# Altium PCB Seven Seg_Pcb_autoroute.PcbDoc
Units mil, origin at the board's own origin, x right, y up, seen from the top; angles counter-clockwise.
Board outline 6000 x 4000 mil, 2 copper layers (Top Layer, Bottom Layer); 31 components, 44 nets, 140 pads, 0 vias.
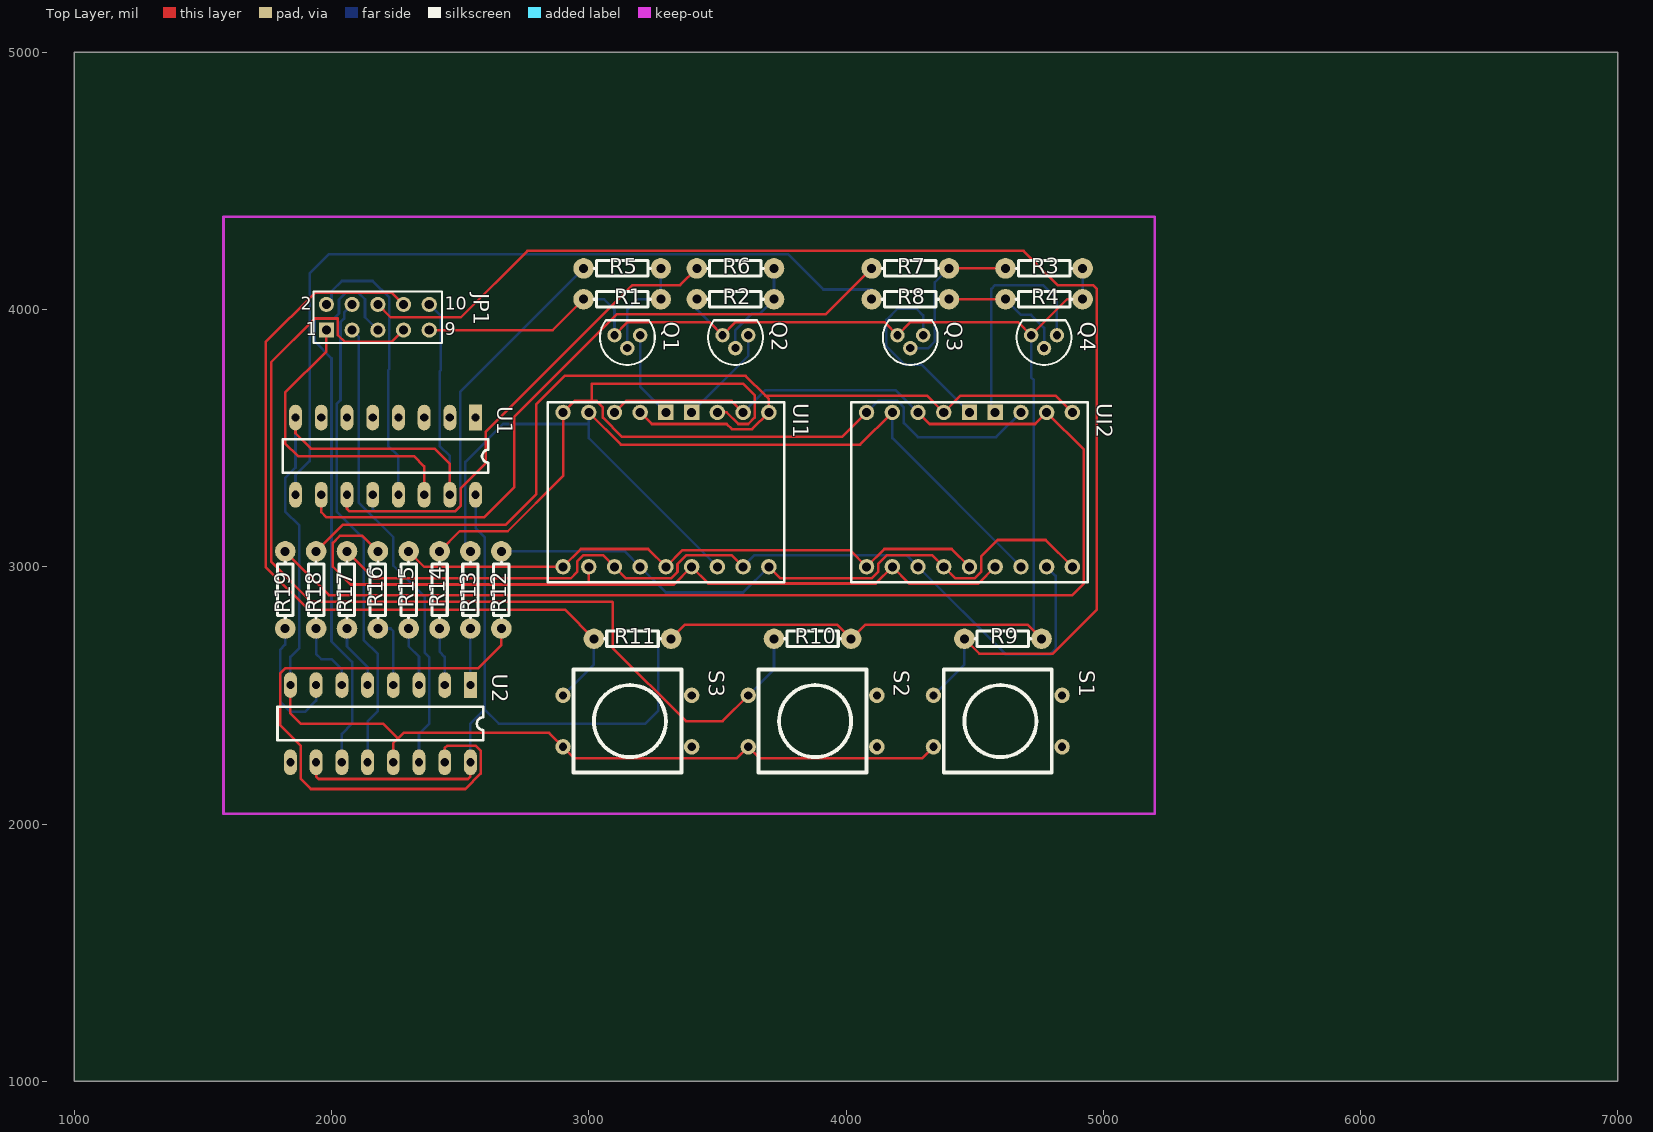
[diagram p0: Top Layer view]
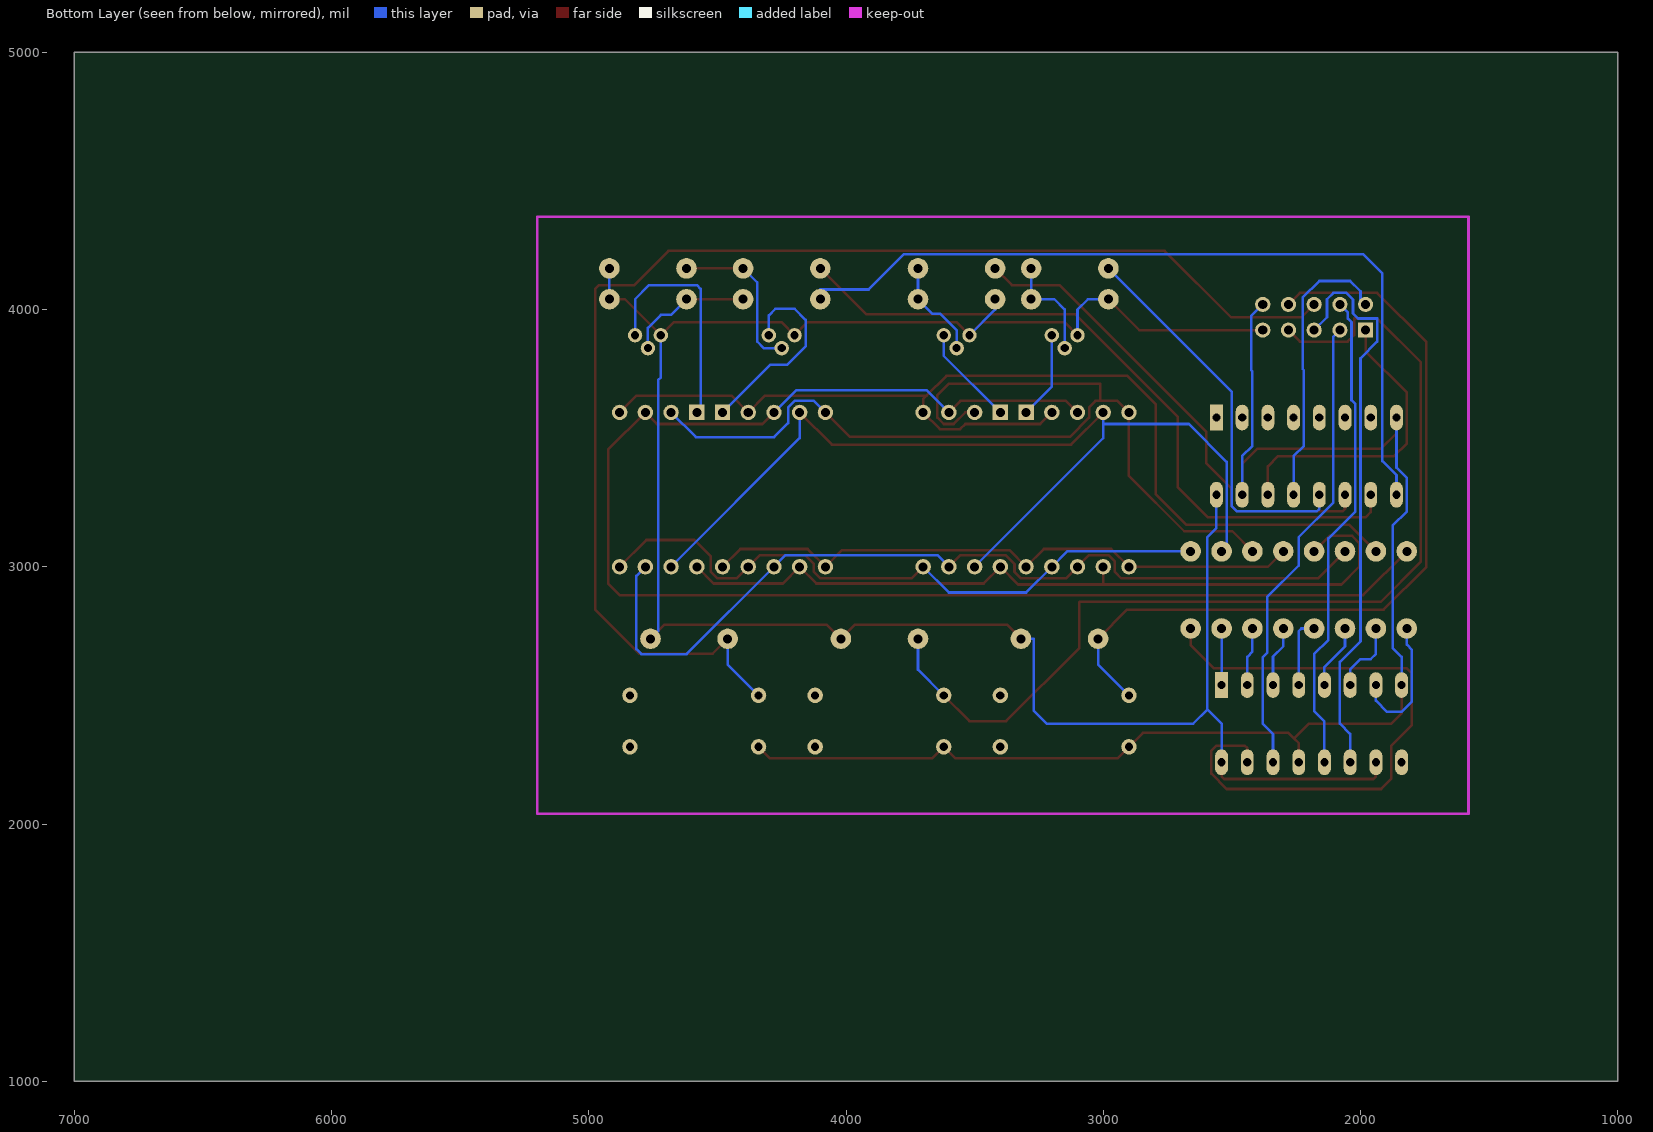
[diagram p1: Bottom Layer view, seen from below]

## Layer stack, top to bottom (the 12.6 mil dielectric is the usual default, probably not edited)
Top Layer: signal copper 1.4
Dielectric: dielectric 12.6, FR-4, Dk 4.8
Bottom Layer: signal copper 1.4

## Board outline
1000,1000 7000,1000 7000,5000 1000,5000

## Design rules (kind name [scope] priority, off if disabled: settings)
Clearance [All] p1: gap=10
ComponentClearance [All] p1: gap=10 collisioncheckmode=0
PolygonConnect [All] p1: connectstyle=Relief reliefconductorwidth=10 reliefentries=4 polygonreliefangle="90 Angle"
RoomDefinition SevenSeg_Sch_04172006 [InComponentClass('SevenSeg_Sch_04172006')] p1: confinementstyle=ConfineIn formatcopy=TRUE outline 1000,1000 7000,1000 7000,4980 1000,4980
RoutingLayers [All] p1: top layer=Horizontal bottom layer=Vertical
RoutingVias [All] p1: holewidth=28 width=50 viastyle="Through Hole" minholewidth=28 minwidth=50 maxholewidth=28 maxwidth=50
SolderMaskExpansion [All] p1: expansion=4
TestPointUsage [All] p1: valid=0 allowmultiple=FALSE
Testpoint [All] p1: side=15 testpointundercomponent=TRUE minsize=40 maxsize=100 preferedsize=60 minholesize=0 maxholesize=40 preferedholesize=32 testpointgrid=1 style=1023 order=-539222988
Width [All] p1: maxlimit=10 minlimit=10 preferedwidth=10
16 further rules are at their usual default settings.

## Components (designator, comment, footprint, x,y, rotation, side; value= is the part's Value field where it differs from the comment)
JP1 "Header 5X2" HDR2X5 1980,3920 r0 top
Q1 "PNP" BC548 3100,3900 r270 top
Q2 "PNP" BC548 3520,3900 r270 top
Q3 "PNP" BC548 4200,3900 r270 top
Q4 "PNP" BC548 4720,3900 r270 top
R1 "10K" RES 3280,4040 r180 top
R2 "10K" RES 3720,4040 r180 top
R3 "10K" RES 4620,4160 r0 top
R4 "10K" RES 4620,4040 r0 top
R5 "10K" RES 2980,4160 r0 top
R6 "10K" RES 3420,4160 r0 top
R7 "10K" RES 4100,4160 r0 top
R8 "10K" RES 4100,4040 r0 top
R9 "10k" RES 4460,2720 r0 top
R10 "10K" RES 3720,2720 r0 top
R11 "10K" RES 3020,2720 r0 top
R12 "220" RES 2660,2760 r90 top
R13 "220" RES 2540,2760 r90 top
R14 "220" RES 2420,2760 r90 top
R15 "220" RES 2300,2760 r90 top
R16 "220" RES 2180,2760 r90 top
R17 "220" RES 2060,2760 r90 top
R18 "220" RES 1940,2760 r90 top
R19 "220" RES 1820,2760 r90 top
S1 "SWITCH PB2" "SWITCH PB2" 4340,2500 r0 top
S2 "SWITCH PB2" "SWITCH PB2" 3620,2500 r0 top
S3 "SWITCH PB2" "SWITCH PB2" 2900,2500 r0 top
U1 "74HC139" DIP16 2560,3580 r270 top
U2 "74HC595" DIP16 2540,2540 r270 top
UI1 "SEVENSEG 2CA" SEVENTSEGMENT2 2900,3600 r0 top
UI2 "SEVENSEG 2CA" SEVENTSEGMENT2 4080,3600 r0 top

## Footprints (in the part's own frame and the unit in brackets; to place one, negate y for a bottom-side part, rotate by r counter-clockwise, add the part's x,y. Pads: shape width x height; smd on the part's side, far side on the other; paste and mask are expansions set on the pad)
BC548 [mil]
  round 56 hole 32: 1(0,0) 2(50,50) 3(0,100)
  silkscreen extent -59,-57 115,157
DIP16 [mil]
  rect 100x50 hole 32: 1(0,0)
  oval 100x50 hole 32: 2(0,-100) 3(0,-200) 4(0,-300) 5(0,-400) 6(0,-500) 7(0,-600) 8(0,-700) 9(300,-700) 10(300,-600) 11(300,-500) 12(300,-400) 13(300,-300) 14(300,-200) 15(300,-100) 16(300,0)
  silkscreen extent 85,-750 215,50
HDR2X5 [mm]
  rect 1.5x1.5 hole 0.9: 1(0,0)
  round 1.5 hole 0.9: 2(0,2.54) 3(2.54,0) 4(2.54,2.54) 5(5.08,0) 6(5.08,2.54) 7(7.62,0) 8(7.62,2.54) 9(10.16,0) 10(10.16,2.54)
  silkscreen extent -1.27,-1.27 11.43,3.81
RES [mil]
  round 80 hole 35: 1(0,0) 2(300,0)
  silkscreen extent 41,-30 259,30
SEVENTSEGMENT2 [mil]
  round 60 hole 35: 1(0,0) 2(100,0) 3(200,0) 4(300,0) 7(600,0) 8(700,0) 9(800,0) 10(800,-600) 11(700,-600) 12(600,-600) 13(500,-600) 14(400,-600) 15(300,-600) 16(200,-600) 17(100,-600) 18(0,-600)
  rect 60x60 hole 35: 5(400,0) 6(500,0)
  silkscreen extent -60,-660 860,40
"SWITCH PB2" [mil]
  round 60 hole 32: 1(0,0) 2(0,-200) 3(500,0) 4(500,-200)
  silkscreen extent 40,-300 460,100

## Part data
JP1: "Header, 5-Pin, Dual row"
Q1 Q2 Q3 Q4: "PNP Transistor"
R1 R2 R3 R4 R5 R6 R7 R8 R9 R10 R11 R12 R13 R14 R15 R16 R17 R18 R19: library part RES
U1: "2-to-4 Decoder"
U2: "8 Bit Shift Register with Output Latches (3 STATE)"

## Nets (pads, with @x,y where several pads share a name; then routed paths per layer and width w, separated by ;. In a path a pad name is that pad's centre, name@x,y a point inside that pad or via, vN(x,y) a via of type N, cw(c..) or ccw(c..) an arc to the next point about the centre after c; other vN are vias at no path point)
COM1: Q4.3 UI2.6 | length 919
  Bottom Layer w10: UI2.6 4565,3600 4565,4080 4580,4095 4765,4095 4820,4040 Q4.3
COM2: Q3.3 UI2.5 | length 781
  Bottom Layer w10: Q3.3 4300,3977 4274,4003 4200,4003 4157,3960 4157,3857 4228,3786 4294,3786 UI2.5
COM3: Q2.3 UI1.6 | length 391.1
  Bottom Layer w10: UI1.6 3620,3820 Q2.3
COM4: Q1.3 UI1.5 | length 341.4
  Bottom Layer w10: Q1.3 3200,3700 UI1.5
DEC0: JP1.2 U1.13 | length 1124.1
  Bottom Layer w10: JP1.2 2000,4020 2000,4071 2040,4111 2160,4111 2225,4046 2225,3769 2220,3764 2220,3470 2260,3430 U1.13
DEC1: JP1.1 U1.14 | length 1193.6
  Top Layer w10: JP1.1 1980,3837 1820,3677 1820,3480 1870,3430 2320,3430 2360,3390 U1.14
DSER: JP1.3 U2.14 | length 1820.8
  Bottom Layer w10: JP1.3 2105,3895 2105,3250 2240,3115 2240,3005 2363,2882 2363,2665 2380,2648 2380,2390 2340,2350 U2.14
GND: JP1.10 S1.2 S2.2 S3.2 U1.8 U1.15 U2.8 U2.13 | length 5557.5
  Top Layer w10: U2.8 1840,2430 1880,2390 2200,2390 2258,2332 ; U1.8 1860,3519 1920,3459 2401,3459 2460,3400 U1.15 ; U2.13 2240,2314 2258,2332 ; S1.2 4295,2255 3665,2255 S2.2 3575,2255 2945,2255 S3.2 2846,2354 2280,2354 2258,2332
  Bottom Layer w10: U2.8 1840,2650 1875,2685 1875,3160 1820,3215 1820,3345 1860,3385 U1.8 ; JP1.10 2425,3975 2425,3765 2420,3760 2420,3470 2460,3430 U1.15
LED1: R19.2 UI1.3 UI1.8 UI2.3 UI2.8 | length 5744.9
  Top Layer w10: R19.2 1990,2890 4880,2890 4925,2935 4925,3455 UI2.8 4735,3555 4325,3555 UI2.3 ; UI1.3 3145,3645 3555,3645 UI1.8
  Bottom Layer w10: UI1.8 3686,3686 4194,3686 UI2.3
LED2: R18.2 UI1.4 UI1.9 UI2.4 UI2.9 | length 4163.8
  Top Layer w10: R18.2 2043,3163 2676,3163 2796,3283 2796,3632 2906,3742 3610,3742 3687,3665 ; UI1.4 3245,3555 3536,3555 3556,3535 3635,3535 UI1.9 3700,3652 3687,3665 ; UI2.9 4815,3665 4445,3665 UI2.4 4315,3665 3687,3665
LED3: R17.2 UI1.11 UI1.16 UI2.11 UI2.16 | length 3490.9
  Top Layer w10: R17.2 2165,2955 2930,2955 2955,2980 2955,3020 2980,3045 3055,3045 UI1.16 3145,2955 3320,2955 3345,2980 3345,3010 3380,3045 3555,3045 UI1.11
  Bottom Layer w10: UI1.11 3645,3045 4235,3045 UI2.16 4620,2660 4795,2660 4815,2680 4815,2965 UI2.11
LED4: R16.2 UI1.13 UI1.17 UI2.13 UI2.17 | length 3112.9
  Top Layer w10: R16.2 2120,3120 2032,3120 2005,3093 2005,3000 2074,2931 3000,2931 ; UI1.17 3000,2931 ; UI2.13 4515,2935 4245,2935 UI2.17 4115,2935 3465,2935 UI1.13 3331,2931 3000,2931
LED5: R15.2 UI1.14 UI1.18 UI2.14 UI2.18 | length 2373
  Top Layer w10: R15.2 2360,3000 UI1.18 2969,3069 3231,3069 UI1.14 3365,3065 4015,3065 UI2.18 4149,3069 4411,3069 UI2.14
LED6: R14.2 UI1.1 UI1.7 UI2.1 UI2.7 | length 3900
  Top Layer w10: R14.2 2498,3138 2685,3138 2900,3353 UI1.1 2945,3645 3012,3645 ; UI1.7 3536.36,3600 3581.36,3555 3620,3555 3645,3580 3645,3667 3600,3712 3012,3712 3012,3645 ; UI2.1 3985,3505 3130,3505 3055,3580 3055,3620 3030,3645 3012,3645
  Bottom Layer w10: UI2.1 4125,3645 4200,3645 4225,3620 4225,3559 4280,3504 4584,3504 UI2.7
LED7: R13.2 UI1.2 UI1.12 UI2.2 UI2.12 | length 3806.7
  Top Layer w10: UI1.2 3125,3475 4055,3475 UI2.2
  Bottom Layer w10: R13.2 2520,3060 2520,3408 2667,3555 3000,3555 ; UI1.2 3000,3555 ; UI1.12 3000,3500 3000,3555 ; UI2.2 4180,3500 UI2.12
LED8: R12.2 UI1.10 UI1.15 UI2.10 UI2.15 | length 2578.4
  Top Layer w10: UI1.10 3745,2955 4100,2955 4125,2980 4125,3010 4160,3045 4335,3045 UI2.15 4425,2955 4500,2955 4525,2980 4525,3040 4589,3104 4776,3104 UI2.10
  Bottom Layer w10: R12.2 3140,3060 UI1.15 3300,2900 3600,2900 UI1.10
LSD1: R8.1 U1.9 | length 3193.6
  Bottom Layer w10: U1.9 1860,3356 1915,3411 1915,4140 1990,4215 3775,4215 3912,4078 4100,4078 R8.1
LSD2: R6.1 U1.11 | length 1921.9
  Top Layer w10: U1.11 2060,3225 2070,3215 2480,3215 2503,3238 2503,3306 2600,3403 2600,3525 3170,4095 3355,4095 R6.1
MSD1: R7.1 U1.10 | length 2777.2
  Top Layer w10: U1.10 1960,3212 1980,3192 2593,3192 2710,3309 2710,3582 3110,3982 3922,3982 R7.1
MSD2: R5.1 U1.12 | length 1531.2
  Bottom Layer w10: U1.12 2160,3225 2170,3215 2480,3215 2500,3235 2500,3680 R5.1
NetQ1_2: Q1.2 R1.1 R5.2 | length 416.6
  Bottom Layer w10: Q1.2 3150,4000 3190,4040 R1.1 R5.2
NetQ2_2: Q2.2 R2.1 R6.2 | length 389.7
  Bottom Layer w10: Q2.2 3570,3920 3633,3983 3663,3983 R2.1 R6.2
NetQ3_2: Q3.2 R3.1 R7.2 | length 633.1
  Top Layer w10: R7.2 R3.1
  Bottom Layer w10: Q3.2 4320,3850 4345,3875 4345,4105 R7.2
NetQ4_2: Q4.2 R4.1 R8.2 | length 495
  Top Layer w10: R8.2 R4.1
  Bottom Layer w10: R4.1 4681,3979 4720,3979 4770,3929 Q4.2
NetR12_1: R12.1 U2.15 | length 2450.5
  Top Layer w10: U2.15 2440,2295 2450,2305 2560,2305 2580,2285 2580,2196 2520,2136 1920,2136 1880,2176 1880,2305 1800,2385 1800,2585 1820,2605 2570,2605 2660,2695 R12.1
NetR13_1: R13.1 U2.1 | length 220
  Bottom Layer w10: U2.1 R13.1
NetR14_1: R14.1 U2.2 | length 228.3
  Bottom Layer w10: R14.1 2420,2670 2440,2650 U2.2
NetR15_1: R15.1 U2.3 | length 236.6
  Bottom Layer w10: R15.1 2300,2691 2340,2651 U2.3
NetR16_1: R16.1 U2.4 | length 274.1
  Bottom Layer w10: R16.1 2230,2760 2240,2750 U2.4
NetR17_1: R17.1 U2.5 | length 253.1
  Bottom Layer w10: R17.1 2060,2690 2140,2610 U2.5
NetR18_1: R18.1 U2.6 | length 284.9
  Bottom Layer w10: R18.1 1940,2661 1960,2641 2000,2641 2040,2601 U2.6
NetR19_1: R19.1 U2.7 | length 527.1
  Bottom Layer w10: R19.1 1820,2697 1800,2677 1800,2476 1840,2436 1896,2436 1940,2480 U2.7
NetU1_2: U1.2
NetU1_3: U1.3
NetU1_4: U1.4
NetU1_5: U1.5
NetU1_6: U1.6
NetU1_7: U1.7
SHCLK: JP1.5 U2.11 | length 2220.7
  Bottom Layer w10: U2.11 2040,2350 2080,2390 2080,2630 2000,2710 2000,3810.47 1935,3875.47 1935,3965 2009,3965 2029,3985 2029,4039 2055,4065 2105,4065 2130,4040 2130,3970 JP1.5
STCLK: JP1.4 U2.12 | length 1887.7
  Bottom Layer w10: JP1.4 2049,3989 2049,3965 2035,3951 2035,3648 2020,3633 2020,3215 2125,3110 2125,2715 2180,2660 2180,2439 2140,2399 U2.12
SW1: JP1.6 R9.1 S1.1 | length 5110.4
  Top Layer w10: JP1.6 2230,3970 2503,3970 2761,4228 4690,4228 4823,4095 4960,4095 4975,4080 4975,2833 4804,2662 4518,2662 R9.1
  Bottom Layer w10: S1.1 4460,2620 R9.1
SW2: JP1.7 R10.1 S2.1 | length 3972.8
  Top Layer w10: JP1.7 2235,3875 2050,3875 2025,3900 2025,3965 1935,3965 1765,3795 1765,3020 1921,2864 3091,2864 3093,2862 3093,2685 3378,2400 3520,2400 S2.1
  Bottom Layer w10: S2.1 3720,2600 R10.1
SW3: JP1.8 R11.1 S3.1 | length 3169.2
  Top Layer w10: JP1.8 2235,4065 1935,4065 1745,3875 1745,2998 1910,2833 2907,2833 R11.1
  Bottom Layer w10: S3.1 3020,2620 R11.1
VCC: JP1.9 Q1.1 Q2.1 Q3.1 Q4.1 R1.2 R2.2 R3.2 R4.2 R9.2 R10.2 R11.2 U1.16 U2.10 U2.16 | length 8764.2
  Top Layer w10: U2.10 1940,2185 1950,2175 2530,2175 2540,2185 U2.16 ; JP1.9 2860,3920 R1.2 ; Q1.1 3151,3951 3469,3951 Q2.1 3571,3951 4149,3951 Q3.1 4251,3951 4669,3951 Q4.1 4860,4040 R4.2 ; R11.2 3375,2775 3965,2775 R10.2 4075,2775 4705,2775 R9.2
  Bottom Layer w10: U2.16 2540,2390 2595,2445 ; U1.16 2560,3150 2595,3115 2595,2445 ; R1.2 3060,4040 3100,4000 Q1.1 ; R11.2 3270,2720 3270,2440 3220,2390 2650,2390 2595,2445 ; R2.2 3420,4000 Q2.1 ; Q4.1 4720,3736 4730,3726 4730,2750 R9.2 ; R4.2 R3.2
pads on no net: S1.3 S1.4 S2.3 S2.4 S3.3 S3.4 U1.1 U2.9

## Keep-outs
Keep-Out Layer:
  lines w10: 1580,2040 5200,2040 5200,4360 1660,4360 1580,4360 1580,2040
